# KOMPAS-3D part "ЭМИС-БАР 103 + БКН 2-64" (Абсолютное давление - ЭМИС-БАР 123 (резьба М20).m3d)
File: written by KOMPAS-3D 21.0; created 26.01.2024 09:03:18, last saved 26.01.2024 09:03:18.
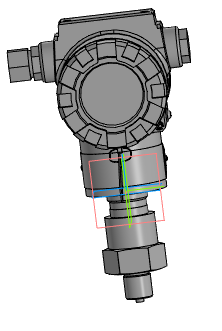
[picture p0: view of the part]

Document properties: Автор: Admin; Организация: office.local; Полное имя файла: S:\Эмис\Инженерный\Расходомеры и фильтры\Задачи\Черненков А.А\ЭМИС-БАР\3D-модели для сайта\Датчики абсолютного давления ЭМИС-БАР\Компоненты\ЭМИС-БАР 123 (резьба М20).m3d

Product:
- Part/product: ЭМИС-БАР 103 + БКН 2-64
    Масса: 5.008587
    Форматы листов документа: A4

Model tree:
1. Операция без истории:1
